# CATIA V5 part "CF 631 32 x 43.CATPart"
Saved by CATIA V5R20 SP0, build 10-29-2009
Part number: CF 631 32 x 43
Definition: NONE
Nomenclature: CF 631 32 x 43
Source: Unknown
Description: CF 631 32 x 43
Bounding box of the stored display mesh (mm): x -13 to 30, y -26.5 to 26.5, z -26.5 to 26.5
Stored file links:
  C:\Users\Utente\Desktop\IO LAVORO\3D X SITO CF\X SITO\CF 631\CF 631 32 x 43.CATPart
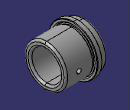
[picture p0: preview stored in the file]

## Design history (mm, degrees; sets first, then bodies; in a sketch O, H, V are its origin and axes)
Body1 "CF 631 32 x 43" (main body)
  Solid1: solid without history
